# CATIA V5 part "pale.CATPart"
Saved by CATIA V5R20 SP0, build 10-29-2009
Part number: pale
Bounding box of the stored display mesh (mm): x 635.778 to 2685.778, y -114.821 to 257.004, z 643.725 to 1623.797
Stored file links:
  D:\thinkmotion-MPB\Dropbox\MMS_GR3\CFAO_2010_bfoltzer\CFAO_bfoltzer\pale.CATPart
  D:\ecole\thinkmotion\Eolienne.CATProduct
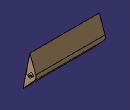
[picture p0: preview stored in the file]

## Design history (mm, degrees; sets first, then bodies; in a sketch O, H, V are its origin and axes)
External parameters (linked from other documents)
  External.rayon_barre = 20 mm
  External.largeur_pale = 300 mm
Set1
  Plane1: linked copy from another document
  Point1 to Point6: linked copy from another document
  Plane2 to Plane4: linked copy from another document
  Point7: linked copy from another document
Body1 (main body)
  Sketch1 on Plane1, origin (635.7782, 0, 0), H (0, 1, 0), V (0, 0, 1)
    line L1 (83.8211, 1623.7969) -> (-114.8213, 643.7249)
    point P1 (83.8211, 1623.7969)
    point P2 (-114.8213, 643.7249)
    line L2 (-114.8213, 643.7249) -> (278.5215, 1074.1682)
    point P3 (-114.8213, 643.7249)
    point P4 (278.5215, 1074.1682)
    line L3 (83.8211, 1623.7969) -> (278.5215, 1074.1682)
    point P5 (83.8211, 1623.7969)
    point P6 (278.5215, 1074.1682)
    reference projected point E1 (278.5215, 1074.1682) from Point1
    reference projected point E2 (-114.8213, 643.7249) from Point2
    reference projected point E3 (-114.8213, 643.7249) from Point2
    reference projected point E4 (83.8211, 1623.7969) from Point3
    reference projected point E5 (278.5215, 1074.1682) from Point7
    reference projected point E6 (83.8211, 1623.7969) from Point3
    coincidence: P4 E1, P3 E2, P2 E3, P1 E4, P6 E5, P5 E6, P1 P5, P2 P3, P4 P6
  Pad1: profile Sketch1, direction (1, 0, 0), up to Plane2
  Fillet1: radius 150 {= External.largeur_pale /2}, on edge [face of Pad1 from Sketch1.L3 | face of Pad1 from Sketch1.L2]
  Sketch2 on Plane1, origin (635.7782, 0, 0), H (0, 1, 0), V (0, 0, 1)
    circle A1 centre (131.5107, 1103.9645) radius 50
    point P1 (131.5107, 1103.9645)
    reference projected point E1 (131.5107, 1103.9645) from Point4
    reference projected point E2 (180.5143, 1094.0324) from Point6
    coincidence: P1 E1, A1 E2
  Pad2: profile Sketch2, direction (1, 0, 0), up to Plane2, opposite side up to Plane3
  Pocket1: profile Sketch2, direction (1, 0, 0), up to Plane1, opposite side up to Plane4
  Sketch3 on start face of Pocket1, origin (685.7782, 857.8838, -926.85), H (0, 1, 0), V (0, 0, -1)
    point P1 (-726.373, -2030.8145)
    reference projected point E1 (-726.373, -2030.8145) from Point4
    coincidence: E1 P1
  Hole1: placed by Sketch3, at (685.7782, 131.5107, 1103.9645) direction (1, 0, 0), diameter 40 {= External.rayon_barre *2}, up to Plane3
